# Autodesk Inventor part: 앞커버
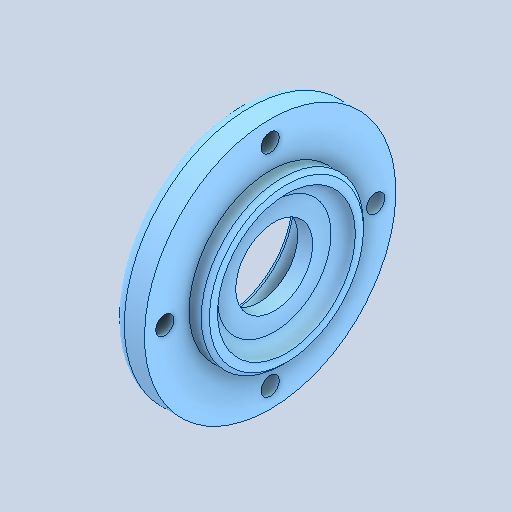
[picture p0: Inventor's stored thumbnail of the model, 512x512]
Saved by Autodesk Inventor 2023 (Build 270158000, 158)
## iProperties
Created: 2024-09
Part Number: 앞커버
Material: 알루미늄 6061
Document SubType Name: Modeling
Designer: home
Density: 2.7 g/cm^3
Appearance: 기본값
Author: jhkim
Sending System: Autodesk Inventor 2025
Preprocessor: ST-DEVELOPER v20
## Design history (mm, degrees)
feature "솔리드1"
node "솔리드2"
